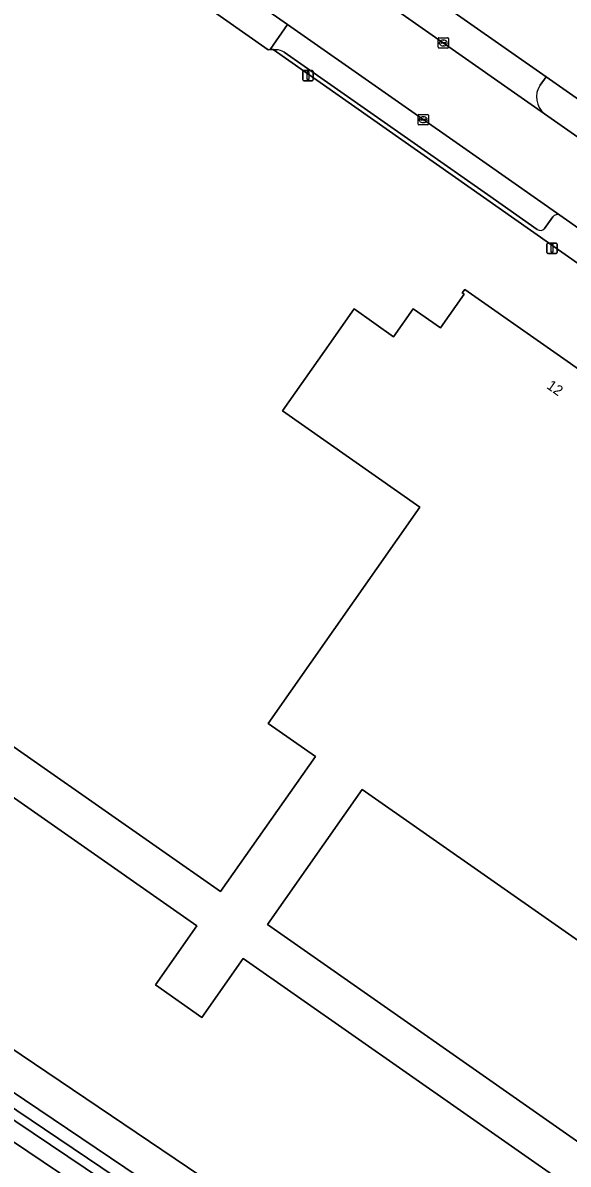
# Model space of a CAD drawing. Extents: x 155018 to 156648, y 383979 to 385733.
# Drawn here: x 155337.5 to 155390.3, y 384711 to 384821.5 of the extents above; entities that cross this region are included whole.
import ezdxf

# ---------------------------------------------------------------- set-up
doc = ezdxf.new("R2010")
doc.units = 0
for name, color, linetype in [('IMGEO_Erf', 7, 'Continuous'), ('IMGEO_Groenvoorziening', 7, 'Continuous'), ('IMGEO_Kolk', 7, 'Continuous'), ('IMGEO_Lichtmast', 7, 'Continuous'), ('IMGEO_Oever', 7, 'Continuous'), ('IMGEO_Pand', 7, 'Continuous'), ('IMGEO_Pand_nummerreeks', 7, 'Continuous'), ('IMGEO_Parkeervlak_open', 7, 'Continuous'), ('IMGEO_Rijbaan_lokaal_gesloten', 7, 'Continuous'), ('IMGEO_Voetpad_open', 7, 'Continuous'), ('IMGEO_Waterloop', 7, 'Continuous')]:
    doc.layers.add(name, color=color, linetype=linetype)

msp = doc.modelspace()

# ---------------------------------------------------------------- linework, layer by layer
at = {"layer": 'IMGEO_Erf'}
for points in [[(155078.52, 385004.55), (155027.41, 384931.04), (155068.82, 384903.06), (155069.31, 384902.73), (155069.77, 384902.42), (155070.29, 384902.07), (155295.33, 384750), (155489.59, 384618.73), (155493.56, 384624.32), (155497.19, 384629.49), (155503.96, 384639.14), (155505.76, 384641.7), (155508.85, 384646.11), (155510.68, 384648.69), (155535.91, 384684.98)], [(155341.14, 384849.34), (155357.1, 384838.1), (155388.18, 384816.31), (155437.86, 384781.52), (155468.11, 384760.26), (155482.74, 384750), (155497.01, 384739.99), (155500, 384737.85), (155500.18, 384737.72), (155505.29, 384734.13), (155525.19, 384720.19), (155529.43, 384717.21), (155537.24, 384711.72), (155537.39, 384711.9)], [(155455.52, 384753.7), (155455.24, 384753.97), (155451.1, 384756.85), (155449.87, 384755.13), (155439.23, 384762.53), (155440.15, 384763.9), (155361.77, 384818.95), (155361.49, 384818.94), (155361.27, 384818.93), (155354.81, 384823.47)], [(155315.34, 384766.33), (155356.66, 384737.42), (155365.85, 384750.48), (155361.29, 384753.68), (155375.95, 384774.63), (155362.67, 384783.95), (155366.73, 384789.73), (155369.6, 384793.83), (155373.4, 384791.12), (155375.33, 384793.83), (155377.96, 384791.99), (155380.25, 384795.27), (155380.07, 384795.4), (155380.3, 384795.72), (155400.99, 384781.22)], [(155390.4, 384708.87), (155358.88, 384730.95), (155354.87, 384725.23), (155350.39, 384728.39), (155354.37, 384734.09), (155313.02, 384763.04)], [(155401.51, 384725.5), (155370.38, 384747.3), (155361.23, 384734.22), (155392.72, 384712.16)]]:
    msp.add_lwpolyline(points, dxfattribs=at)
at = {"layer": 'IMGEO_Groenvoorziening'}
for points in [[(155117.29, 384866.73), (155188.59, 384818.4), (155275.37, 384759.29), (155397.34, 384677), (155402.02, 384673.84), (155421.28, 384660.85), (155457.87, 384636.86), (155479.18, 384622.39), (155480.37, 384621.21), (155480.58, 384620.35), (155479.94, 384619.28), (155485.92, 384615.12), (155487.18, 384616.15), (155488.31, 384617.33), (155489.29, 384618.64), (155489.46, 384618.53), (155489.59, 384618.73), (155295.33, 384750), (155070.29, 384902.07)], [(155051.94, 384898.82), (155452.62, 384628.74), (155476.25, 384612.78), (155476.44, 384612.75), (155478.07, 384612.6), (155479.69, 384612.67), (155481.3, 384612.94), (155482.88, 384613.45), (155484.38, 384614.15), (155485.79, 384615.02), (155485.92, 384615.12), (155479.94, 384619.28), (155479.94, 384619.27), (155479.35, 384618.47), (155478.16, 384618.25), (155475.96, 384619.11), (155396.84, 384672.62), (155274.45, 384755.08), (155190.89, 384811.75), (155114.7, 384863.03)]]:
    msp.add_lwpolyline(points, dxfattribs=at)
at = {"layer": 'IMGEO_Kolk'}
for p, q in [((155377.73, 384819.17), (155377.73, 384820.02)), ((155377.8, 384820.09), (155378.66, 384820.09)), ((155378.73, 384820.02), (155378.73, 384819.17)), ((155378.66, 384819.09), (155377.8, 384819.09)), ((155377.99, 384819.59), (155377.99, 384819.6)), ((155378.03, 384819.64), (155378.43, 384819.64)), ((155378.43, 384819.55), (155378.03, 384819.55)), ((155378.24, 384819.31), (155378.21, 384819.31)), ((155378.22, 384819.87), (155378.24, 384819.87)), ((155378.47, 384819.6), (155378.47, 384819.59)), ((155375.79, 384811.73), (155375.79, 384812.58)), ((155375.86, 384812.66), (155376.72, 384812.66)), ((155376.28, 384812.43), (155376.3, 384812.43)), ((155376.79, 384812.58), (155376.79, 384811.73)), ((155376.72, 384811.65), (155375.86, 384811.65)), ((155376.05, 384812.15), (155376.05, 384812.16)), ((155376.09, 384812.2), (155376.49, 384812.2)), ((155376.48, 384812.11), (155376.09, 384812.11)), ((155376.3, 384811.88), (155376.27, 384811.88)), ((155376.53, 384812.16), (155376.53, 384812.15))]:
    msp.add_line(p, q, dxfattribs=at)
for points in [[(155377.73, 384819.17), (155377.73, 384820.02)], [(155377.8, 384820.09), (155378.66, 384820.09)], [(155378.73, 384820.02), (155378.73, 384819.17)], [(155378.66, 384819.09), (155377.8, 384819.09)], [(155375.79, 384811.73), (155375.79, 384812.58)], [(155375.86, 384812.66), (155376.72, 384812.66)], [(155376.79, 384812.58), (155376.79, 384811.73)], [(155376.72, 384811.65), (155375.86, 384811.65)]]:
    msp.add_lwpolyline(points, dxfattribs=at)
for centre, radius, start, end in [((155377.81, 384820.02), 0.0765, 91.552, 178.448), ((155377.81, 384820.02), 0.0765, 91.552, 178.448), ((155378.65, 384820.02), 0.0765, 1.552, 88.448), ((155378.65, 384820.02), 0.0765, 1.552, 88.448), ((155377.81, 384819.17), 0.0765, 181.552, 268.448), ((155377.81, 384819.17), 0.0765, 181.552, 268.448), ((155378.03, 384819.6), 0.0403, 85.8775, 175.7526), ((155378.02, 384819.59), 0.0366, 178.938, 274.7102), ((155378.43, 384819.6), 0.0386, 1.7309, 96.639), ((155378.43, 384819.59), 0.043, 264.8664, 352.4533), ((155378.65, 384819.17), 0.0765, 271.552, 358.448), ((155378.65, 384819.17), 0.0765, 271.552, 358.448), ((155375.86, 384812.58), 0.0765, 91.552, 178.448), ((155375.86, 384812.58), 0.0765, 91.552, 178.448), ((155376.71, 384812.58), 0.0765, 1.552, 88.448), ((155376.71, 384812.58), 0.0765, 1.552, 88.448), ((155375.86, 384811.73), 0.0765, 181.552, 268.448), ((155375.86, 384811.73), 0.0765, 181.552, 268.448), ((155376.09, 384812.16), 0.0403, 85.8775, 175.7526), ((155376.08, 384812.15), 0.0366, 178.938, 274.7102), ((155376.49, 384812.15), 0.043, 264.8664, 352.4533), ((155376.49, 384812.16), 0.0386, 1.7309, 96.639), ((155376.71, 384811.73), 0.0765, 271.552, 358.448), ((155376.71, 384811.73), 0.0765, 271.552, 358.448)]:
    msp.add_arc(centre, radius, start, end, dxfattribs=at)
for centre, major_axis, ratio, start_param, end_param in [((155378.22, 384819.59), (-0.387, 0.002), 0.722429, 4.712389, 7.853982), ((155378.24, 384819.59), (-0.39, 0.002), 0.717154, 1.570796, 4.712389), ((155376.28, 384812.15), (-0.387, 0.002), 0.722429, 4.712389, 7.853982), ((155376.3, 384812.15), (-0.39, 0.002), 0.717154, 1.570796, 4.712389)]:
    msp.add_ellipse(centre, major_axis=major_axis, ratio=ratio, start_param=start_param, end_param=end_param, dxfattribs=at)
at = {"layer": 'IMGEO_Lichtmast'}
for p, q in [((155364.65, 384816.03), (155364.65, 384816.83)), ((155364.65, 384816.83), (155364.65, 384816.03)), ((155364.75, 384816.93), (155365.53, 384816.93)), ((155365.53, 384816.93), (155364.75, 384816.93)), ((155365.63, 384816.83), (155365.63, 384816.03)), ((155365.63, 384816.03), (155365.63, 384816.83)), ((155365.53, 384815.93), (155364.75, 384815.93)), ((155364.75, 384815.93), (155365.53, 384815.93)), ((155388.26, 384799.31), (155388.26, 384800.11)), ((155388.26, 384800.11), (155388.26, 384799.31)), ((155388.36, 384800.21), (155389.15, 384800.21)), ((155389.15, 384800.21), (155388.36, 384800.21)), ((155389.25, 384800.11), (155389.25, 384799.31)), ((155389.25, 384799.31), (155389.25, 384800.11)), ((155389.15, 384799.21), (155388.36, 384799.21)), ((155388.36, 384799.21), (155389.15, 384799.21))]:
    msp.add_line(p, q, dxfattribs=at)
for points in [[(155365.07, 384816.8), (155365.22, 384816.8), (155365.22, 384816.05), (155365.07, 384816.05), (155365.07, 384816.8)], [(155388.68, 384800.09), (155388.83, 384800.09), (155388.83, 384799.34), (155388.68, 384799.34), (155388.68, 384800.09)]]:
    msp.add_lwpolyline(points, dxfattribs=at)
for centre, start, end in [((155364.75, 384816.83), 90, 180), ((155364.75, 384816.83), 90, 180), ((155365.53, 384816.83), 0, 90), ((155365.53, 384816.83), 360, 90), ((155364.75, 384816.03), 180, 270), ((155364.75, 384816.03), 180, 270), ((155365.53, 384816.03), 270, 0), ((155365.53, 384816.03), 270, 0), ((155388.36, 384800.11), 90, 180), ((155388.36, 384800.11), 90, 180), ((155389.15, 384800.11), 0, 90), ((155389.15, 384800.11), 360, 90), ((155388.36, 384799.31), 180, 270), ((155388.36, 384799.31), 180, 270), ((155389.15, 384799.31), 270, 0), ((155389.15, 384799.31), 270, 0)]:
    msp.add_arc(centre, 0.1, start, end, dxfattribs=at)
at = {"layer": 'IMGEO_Oever'}
msp.add_lwpolyline([(155071.77, 384897.16), (155070.79, 384895.69), (155107.86, 384870.72), (155189.77, 384815.43), (155286.77, 384750.06), (155396.63, 384675.94), (155397.34, 384677), (155275.37, 384759.29), (155188.59, 384818.4), (155117.29, 384866.73)], close=True, dxfattribs=at)
msp.add_lwpolyline([(155190.89, 384811.75), (155274.45, 384755.08), (155396.84, 384672.62), (155475.96, 384619.11), (155478.16, 384618.25), (155479.35, 384618.47), (155479.94, 384619.27), (155479.94, 384619.28), (155480.58, 384620.35), (155480.37, 384621.21), (155479.18, 384622.39), (155457.87, 384636.86), (155421.28, 384660.85), (155402.02, 384673.84), (155401.32, 384672.78), (155449.57, 384640.25), (155478.98, 384620.38), (155478.52, 384619.62), (155459.21, 384632.67), (155408.46, 384666.96), (155400.85, 384672.08), (155396.16, 384675.24), (155275.77, 384756.26), (155189.8, 384814.33)], dxfattribs=at)
at = {"layer": 'IMGEO_Pand'}
for points in [[(155400.99, 384781.22), (155380.3, 384795.72), (155380.07, 384795.4), (155380.25, 384795.27), (155377.96, 384791.99), (155375.33, 384793.83), (155373.4, 384791.12), (155369.6, 384793.83), (155366.73, 384789.73), (155362.67, 384783.95), (155375.95, 384774.63), (155361.29, 384753.68), (155365.85, 384750.48), (155356.66, 384737.42), (155315.34, 384766.33)], [(155313.02, 384763.04), (155354.37, 384734.09), (155350.39, 384728.39), (155354.87, 384725.23), (155358.88, 384730.95), (155390.4, 384708.87)], [(155392.72, 384712.16), (155361.23, 384734.22), (155370.38, 384747.3), (155401.51, 384725.5)]]:
    msp.add_lwpolyline(points, dxfattribs=at)
at = {"layer": 'IMGEO_Parkeervlak_open'}
for points in [[(155389.5, 384802.9), (155382.37, 384807.91), (155363.16, 384821.38), (155361.49, 384818.94), (155361.77, 384818.95), (155362.07, 384818.93)], [(155362.83, 384818.69), (155382.5, 384804.9), (155387.32, 384801.53)], [(155388.02, 384801.61), (155388.83, 384802.76)]]:
    msp.add_lwpolyline(points, dxfattribs=at)
for centre, radius, start, end in [((155362.04, 384817.49), 1.44, 56.6794, 89.0208), ((155389.24, 384802.47), 0.498, 58.8068, 145.2301), ((155387.63, 384801.95), 0.521, 233.6813, 319.1422)]:
    msp.add_arc(centre, radius, start, end, dxfattribs=at)
at = {"layer": 'IMGEO_Rijbaan_lokaal_gesloten'}
for points in [[(155494.89, 384737.79), (155477.48, 384750), (155467.97, 384756.67), (155434.55, 384780.11), (155388.02, 384812.73), (155353.81, 384836.72)], [(155356.56, 384826), (155363.16, 384821.38), (155382.37, 384807.91), (155389.5, 384802.9), (155391.66, 384801.39), (155397.71, 384797.16), (155436.33, 384770.06), (155438.8, 384768.32), (155441.64, 384766.32), (155456.24, 384756.11), (155456.59, 384755.85), (155464.92, 384750), (155479.51, 384739.76), (155484.42, 384736.31)]]:
    msp.add_lwpolyline(points, dxfattribs=at)
at = {"layer": 'IMGEO_Voetpad_open'}
for points in [[(155387.59, 384815.49), (155388.18, 384816.31), (155357.1, 384838.1), (155356.52, 384837.25)], [(155353.81, 384836.72), (155388.02, 384812.73)], [(155362.07, 384818.93), (155361.77, 384818.95), (155440.15, 384763.9)], [(155387.32, 384801.53), (155382.5, 384804.9), (155362.83, 384818.69)], [(155437.29, 384780.64), (155437.86, 384781.52), (155388.18, 384816.31), (155387.59, 384815.49)], [(155388.02, 384812.73), (155434.55, 384780.11)], [(155388.83, 384802.76), (155388.02, 384801.61)], [(155391.66, 384801.39), (155389.5, 384802.9)]]:
    msp.add_lwpolyline(points, dxfattribs=at)
msp.add_lwpolyline([(155354.81, 384823.47), (155361.27, 384818.93), (155361.49, 384818.94), (155363.16, 384821.38), (155356.56, 384826)], close=True, dxfattribs=at)
for centre, radius, start, end in [((155362.04, 384817.49), 1.44, 56.6794, 89.0208), ((155389.34, 384814.35), 2.09, 146.8314, 230.817), ((155389.34, 384814.35), 2.09, 146.8314, 230.817), ((155389.24, 384802.47), 0.498, 58.8068, 145.2301), ((155387.63, 384801.95), 0.521, 233.6813, 319.1422)]:
    msp.add_arc(centre, radius, start, end, dxfattribs=at)
at = {"layer": 'IMGEO_Waterloop'}
msp.add_lwpolyline([(155070.24, 384894.86), (155107.27, 384869.77), (155189.8, 384814.33), (155275.77, 384756.26), (155396.16, 384675.24), (155396.63, 384675.94), (155286.77, 384750.06), (155189.77, 384815.43), (155107.86, 384870.72), (155070.79, 384895.69)], close=True, dxfattribs=at)

# ---------------------------------------------------------------- texts
at = {"layer": 'IMGEO_Pand_nummerreeks'}
msp.add_text('12', height=1, rotation=324.9865, dxfattribs=at).set_placement((155388.15, 384786.2))

doc.saveas('drawing.dxf')
